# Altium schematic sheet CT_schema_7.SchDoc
size 374 x 245 mm
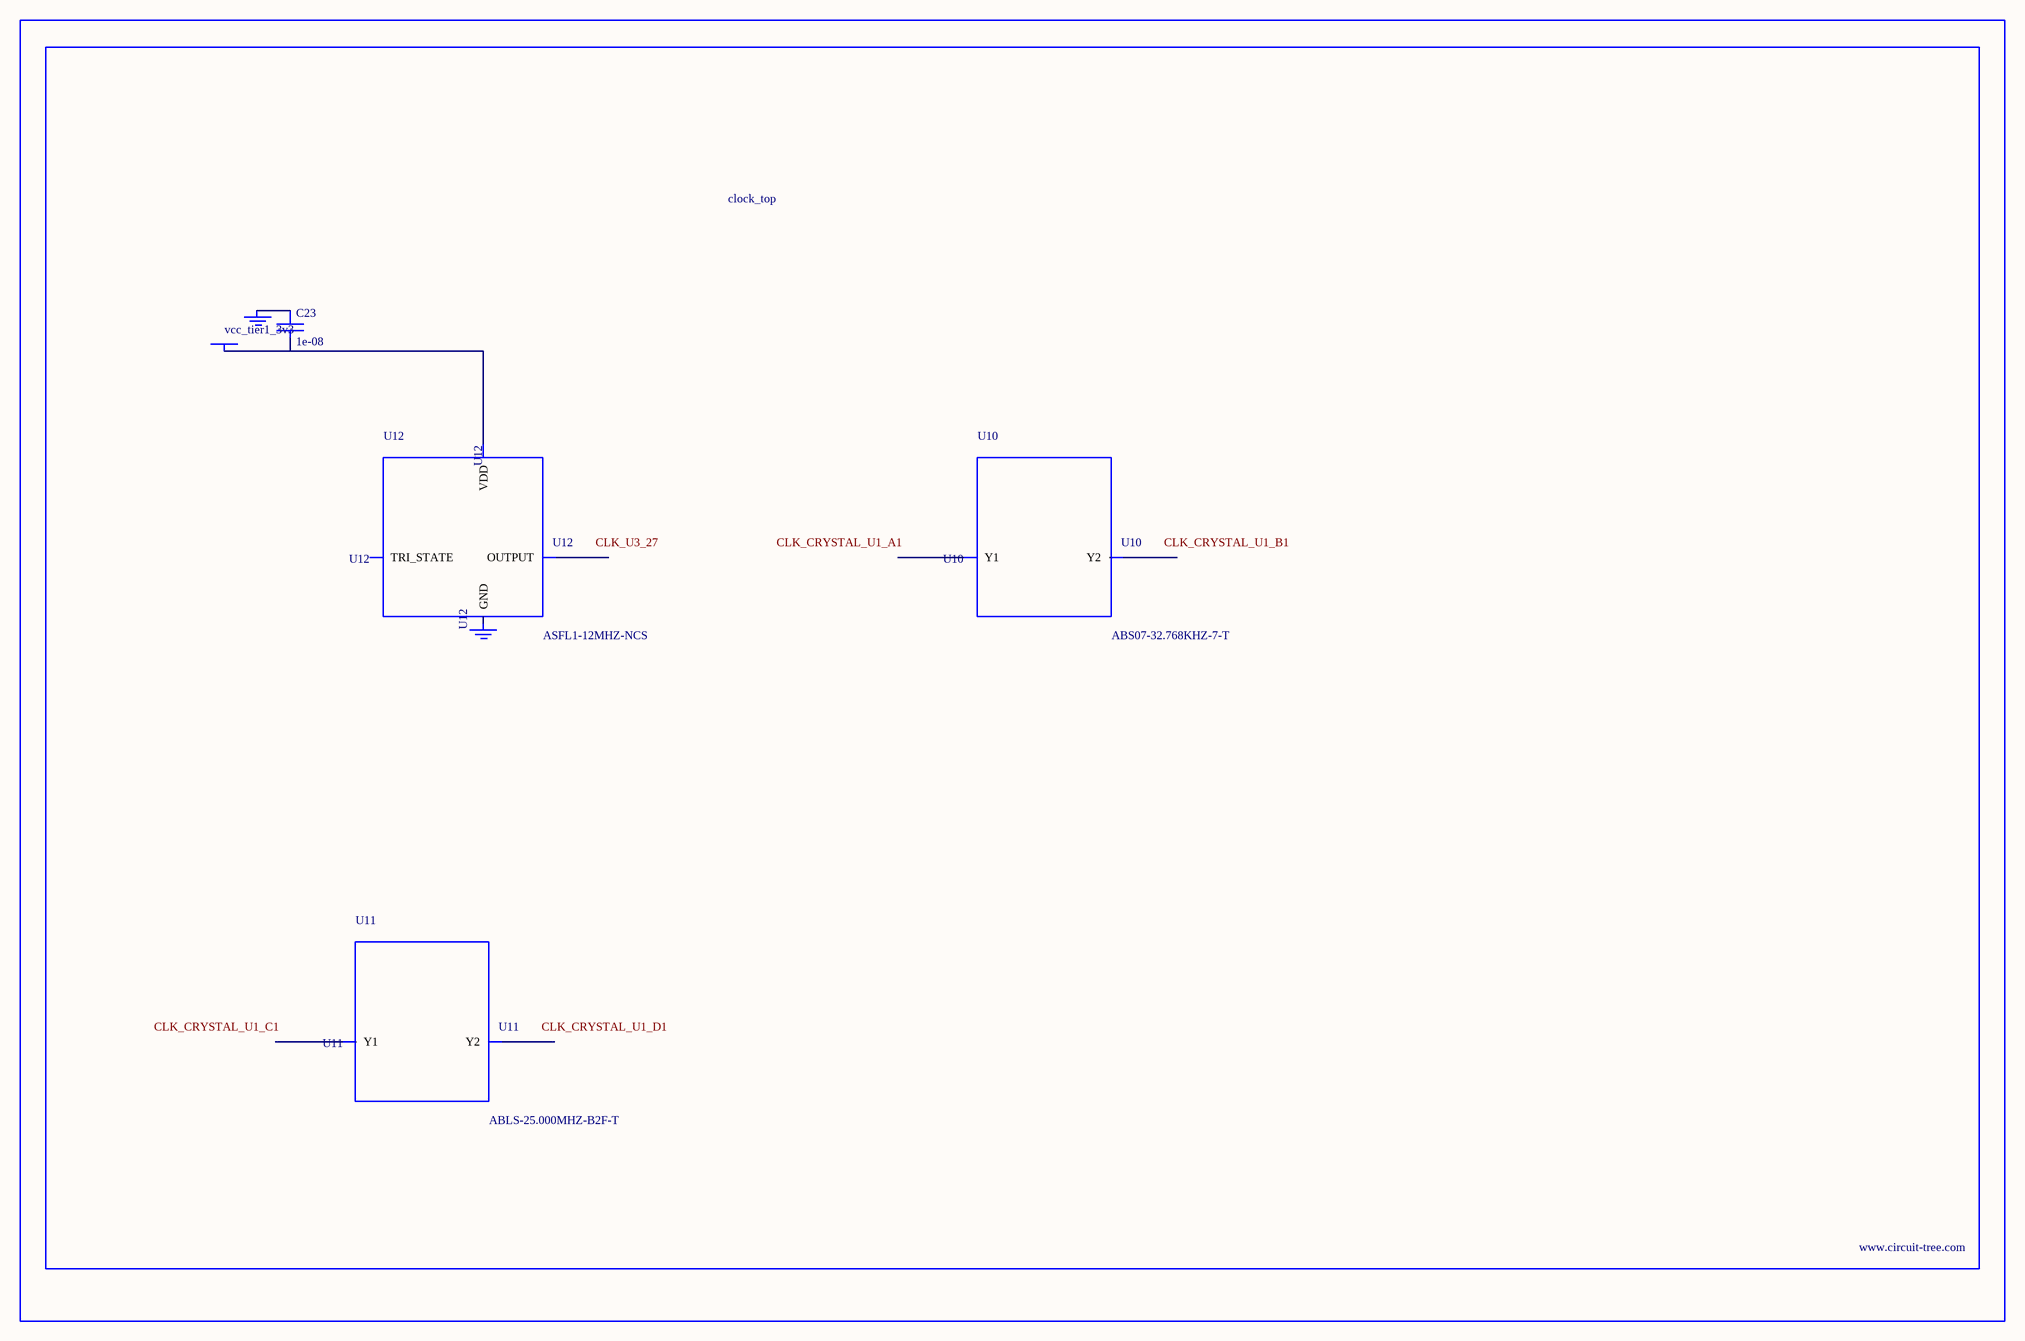
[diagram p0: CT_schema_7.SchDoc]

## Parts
BORDER6  (no value)
C23  1e-08  [C0402]
GND_INSTANCE_6_0  (no value)
GND_INSTANCE_6_1  (no value)
POWER_INSTANCE_6_0  vcc_tier1_3v3
U10  ABS07-32.768KHZ-7-T  [ABS07-32.768KHZ-7-T]
U11  ABLS-25.000MHZ-B2F-T  [ABLS-25.000MHZ-B2F-T]
U12  ASFL1-12MHZ-NCS  [ASFL1]

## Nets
NetC23_1: C23.1 GND_INSTANCE_6_0.0(GND)
NetC23_2: C23.2 POWER_INSTANCE_6_0.0(PWR) U12.4(VDD)

Not connected (* = marked no-connect by the designer): GND_INSTANCE_6_1 0(GND); U10 1(Y1) 2(Y2); U11 1(Y1) 2(Y2); U12 1(TRI_STATE) 2(GND) 3(OUTPUT)

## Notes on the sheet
- Labels drawn without touching a wire or pin: CLK_CRYSTAL_U1_A1, CLK_CRYSTAL_U1_B1, CLK_CRYSTAL_U1_C1, CLK_CRYSTAL_U1_D1, CLK_U3_27

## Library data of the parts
BORDER6 = BORDER_PAGE6
C23 = C0402C103K3RAC
GND_INSTANCE_6_0 GND_INSTANCE_6_1 = GND
POWER_INSTANCE_6_0 = PWR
